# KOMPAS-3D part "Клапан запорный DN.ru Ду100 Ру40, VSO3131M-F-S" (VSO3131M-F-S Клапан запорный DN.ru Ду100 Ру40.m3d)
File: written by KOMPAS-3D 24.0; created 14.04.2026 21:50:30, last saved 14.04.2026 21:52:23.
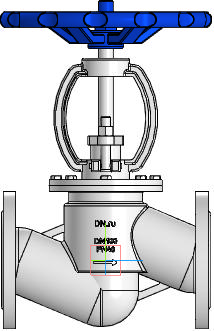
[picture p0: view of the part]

Document properties: Автор: R2D2; Полное имя файла: E:\Работа\Зайцев\VSO3131M-F-S Клапан запорный DN.ru Ду15-100 Ру40\DN100\VSO3131M-F-S Клапан запорный DN.ru Ду100 Ру40.m3d

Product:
- Part/product: Клапан запорный DN.ru Ду100 Ру40  | designation VSO3131M-F-S
    Масса: 36.7
    Раздел спецификации: Прочие изделия
    Примечание: D090-02145

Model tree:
1. Операция без истории:1

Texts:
  VSO3131M-F-S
